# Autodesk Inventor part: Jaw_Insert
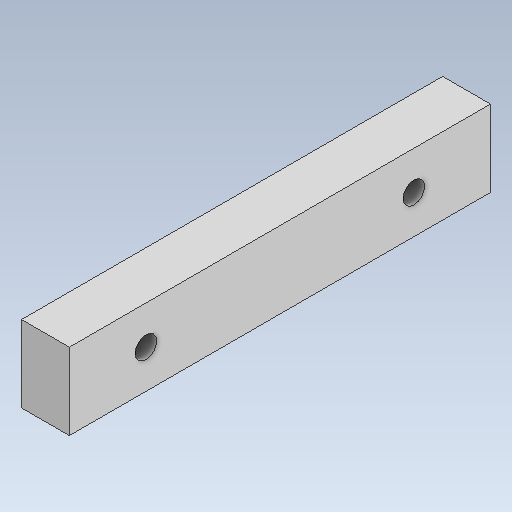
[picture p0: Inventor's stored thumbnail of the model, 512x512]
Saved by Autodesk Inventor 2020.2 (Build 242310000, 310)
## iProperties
Created: 2019-12
Part Number: Jaw_Insert
Material: Generic
Document SubType Name: Modeling
Designer: Patrick Everitt
Density: 1 g/cm^3
Appearance: Default
Description: 3/4 x 1 A2 5 3/4 Lg
Author: Patrick Everitt
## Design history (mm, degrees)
sketch "Sketch1"
  geometry: L1 (0, 0)-(0, 25.4); L2 (0, 25.4)-(15.875, 25.4); L3 (15.875, 25.4)-(15.875, 0); L4 (15.875, 0)-(0, 0)
  constraints: 8 end point, 3 perpendicular, 1 vertical
  dimensions: "d0" = 25.4 distance of L2.end L3.end; "d1" = 15.875 distance of L1.end L2.end
extrude "Extrusion1" new body sketch "Sketch1" distance "d2" = 139.7; taper "d3" = 0 deg
sketch "Sketch2"
  geometry: 3 further points
  dimensions: "d4" = 25.4 horizontal distance of point (25.4, 12.7) point (0, 0); "d5" = 88.9 distance of point (114.3, 12.7) point (25.4, 12.7); "d6" = 12.7 vertical distance of point (0, 0) point (25.4, 12.7)
hole "Hole1" sketch "Sketch2" at (25.4, 12.7), (114.3, 12.7) diameter "d7" = 7.1374; stored, may be unused: countersink angle "d11" = 82 deg, drill point angle "d13" = 118 deg; dims "d8" = 19.05, "d9" = 10.3124, "d10" = 7.9375, "d12" = 25.4
body "Solid1"
